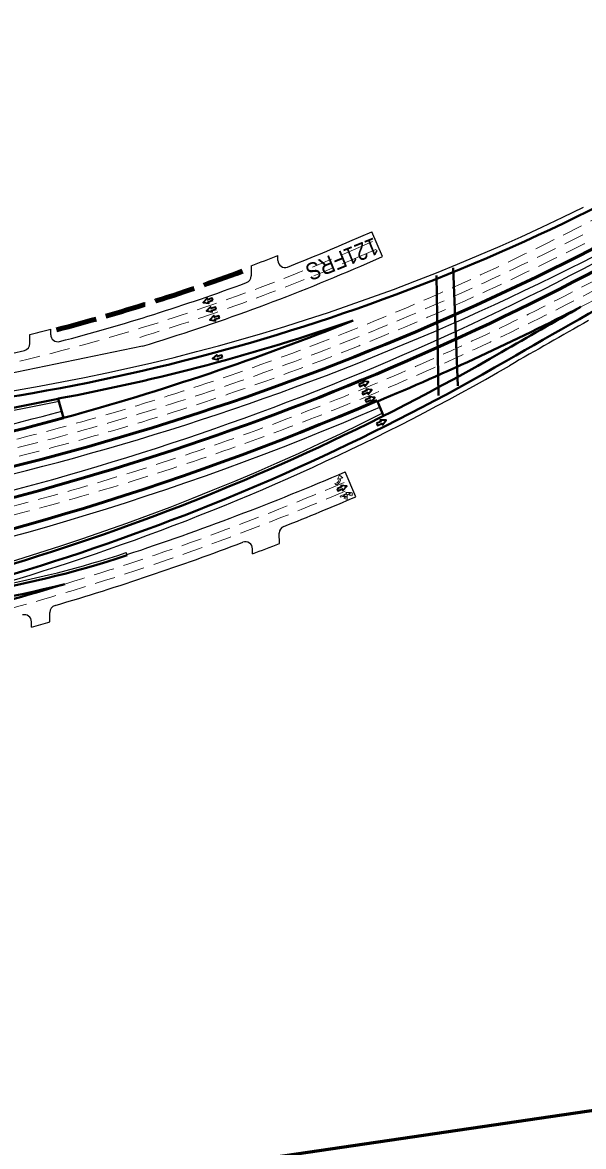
# Model space of a CAD drawing. Extents: x 2329387 to 2347382, y 6951580 to 6987999.
# Drawn here: x 2336392 to 2337180, y 6964242 to 6965820 of the extents above; entities that cross this region are included whole.
import ezdxf

# ---------------------------------------------------------------- set-up
doc = ezdxf.new("R2010")
doc.units = 0
doc.header["$LTSCALE"] = 9.6
doc.header["$PDMODE"] = 32
doc.header["$PDSIZE"] = 4.8
doc.linetypes.add('LONG_DASHED', pattern=[7.5, 6, -1.5])
doc.linetypes.add('MEDIUM_DASHED', pattern=[4.5, 3, -1.5])
for name, color, linetype, lineweight in [('26', 7, 'Continuous', 53), ('27', 7, 'Continuous', 40), ('28', 7, 'Continuous', 25), ('30', 7, 'Continuous', 13), ('41', 7, 'Continuous', 35), ('50', 7, 'MEDIUM_DASHED', 13), ('59', 7, 'LONG_DASHED', 90), ('62', 7, 'Continuous', 60), ('63', 7, 'Continuous', 25)]:
    doc.layers.add(name, color=color, linetype=linetype, lineweight=lineweight)
doc.layers.add('40', color=7, linetype='Continuous')

msp = doc.modelspace()

# ---------------------------------------------------------------- linework, layer by layer
at = {"layer": '26'}
for centre, radius, start, end in [((2335453.211, 6968900.408), 3817.469, 278.35573, 300.65952), ((2335400.739, 6968870.593), 3843.719, 278.81536, 299.60537), ((2335348.901, 6968850.035), 3879.719, 279.60989, 293.40387), ((2335453.211, 6968900.408), 3769.469, 278.35579, 285.32717)]:
    msp.add_arc(centre, radius, start, end, dxfattribs=at)
at = {"layer": '26', "lineweight": 25}
for centre, radius, start, end in [((2335453.211, 6968900.408), 3827.469, 278.35573, 300.65952), ((2335400.739, 6968870.593), 3833.719, 278.81536, 299.60537), ((2335348.901, 6968850.035), 3889.719, 279.60989, 293.40175), ((2335453.211, 6968900.408), 3759.469, 278.35579, 285.32717)]:
    msp.add_arc(centre, radius, start, end, dxfattribs=at)
at = {"layer": '27'}
for p, q in [((2336442.194, 6965292.014), (2336449.596, 6965265.01)), ((2336898.919, 6965267.974), (2336890.472, 6965288.287))]:
    msp.add_line(p, q, dxfattribs=at)
at = {"layer": '27', "lineweight": 25}
msp.add_line((2336538.921, 6965072.242), (2336537.666, 6965076.04), dxfattribs=at)
at = {"layer": '27'}
for centre, radius, start, end in [((2339406.145, 6959556.474), 7976, 170.51466, 170.51466), ((2335914.539, 6968122.19), 2864.789, 275.56071, 300.68463), ((2342801.708, 6955421.615), 11459.156, 118.82398, 120.00238), ((2335400.739, 6968870.593), 3879.719, 292.58041, 297.23352), ((2342801.708, 6955421.615), 11473.156, 119.36174, 120.00238), ((2335914.539, 6968122.19), 2878.789, 280.56067, 289.09494), ((2335453.211, 6968900.408), 3769.469, 285.32717, 291.85272), ((2335434.579, 6968180.635), 3260.044, 278.35573, 300.00238), ((2335434.579, 6968180.635), 3274.044, 278.35573, 300.00238), ((2338670.145, 6954065.803), 11445.156, 101.22505, 102.56422), ((2336093.959, 6966419.035), 1418.394, 278.65967, 288.28285), ((2336093.959, 6966419.035), 1432.394, 274.60744, 284.44642), ((2335351.623, 6968665.906), 3796.719, 283.76869, 286.8364)]:
    msp.add_arc(centre, radius, start, end, dxfattribs=at)
at = {"layer": '27', "lineweight": 25}
for centre, radius, start, end in [((2335914.539, 6968122.19), 2856.789, 275.56071, 296.28739), ((2342801.708, 6955421.615), 11451.156, 119.36378, 120.00238), ((2335434.579, 6968180.635), 3282.044, 278.35573, 300.00238), ((2338670.145, 6954065.803), 11441.156, 101.22361, 102.56422), ((2335434.579, 6968180.635), 3256.044, 278.35573, 296.69097), ((2336093.959, 6966419.035), 1414.394, 280.11263, 288.28285)]:
    msp.add_arc(centre, radius, start, end, dxfattribs=at)
at = {"layer": '28'}
for p, q in [((2336851.795, 6965512.989), (2336882.568, 6965526.287)), ((2336897.641, 6965491.404), (2336882.568, 6965526.287)), ((2336750.537, 6965486.075), (2336750.485, 6965492.951)), ((2336866.861, 6965478.104), (2336897.641, 6965491.404)), ((2336712.979, 6965478.605), (2336713.101, 6965464.352)), ((2336431.554, 6965381.835), (2336431.527, 6965389.584)), ((2336402.274, 6965369.41), (2336402.235, 6965382.133)), ((2336560.342, 6965365.66), (2336302.2, 6965312.166)), ((2336860.023, 6965154.458), (2336845.025, 6965189.373)), ((2336752.637, 6965088.761), (2336752.575, 6965103.38)), ((2336714.981, 6965074.24), (2336714.928, 6965081.203)), ((2336404.711, 6964971.341), (2336404.603, 6964979.007)), ((2336430.494, 6964978.787), (2336430.436, 6964992.096))]:
    msp.add_line(p, q, dxfattribs=at)
for centre, radius, start, end in [((2335715.816, 6968141.837), 2863.789, 291.47419, 293.37016), ((2335715.816, 6968141.837), 2843.789, 290.52683, 291.33588), ((2336760.537, 6965486.15), 10, 180.43476, 291.47419), ((2335715.816, 6968141.837), 2901.789, 286.92001, 293.37001), ((2335715.816, 6968141.837), 2863.789, 284.7325, 290.24016), ((2336703.101, 6965464.267), 10, 290.24015, 0.48871), ((2335715.816, 6968141.837), 2843.789, 283.9677, 284.57665), ((2336441.553, 6965381.87), 10, 180.19786, 284.7325), ((2335715.816, 6968141.837), 2863.789, 278.38524, 283.71181), ((2336392.274, 6965369.38), 10, 283.71182, 0.17378), ((2335351.623, 6968665.906), 3783.719, 288.28285, 293.24673), ((2335351.623, 6968665.906), 3821.719, 291.60646, 293.24673), ((2336762.575, 6965103.423), 10, 111.60646, 180.24506), ((2335351.623, 6968665.906), 3821.719, 286.50851, 290.68224), ((2336704.928, 6965081.127), 10, 0.43315, 110.68224), ((2335351.623, 6968665.906), 3841.719, 290.78622, 291.38814), ((2336440.436, 6964992.14), 10, 106.50851, 180.24816), ((2336394.604, 6964978.866), 10, 0.81008, 105.79501), ((2335351.623, 6968665.906), 3841.719, 285.90951, 286.30975)]:
    msp.add_arc(centre, radius, start, end, dxfattribs=at)
at = {"layer": '30'}
for points in [[(2336836.724, 6965180.042), (2336834.047, 6965178.979), (2336837.085, 6965184.775)], [(2336837.085, 6965184.775), (2336841.867, 6965180.819), (2336838.801, 6965180.38)], [(2336833.255, 6965171.725), (2336831.472, 6965171.014), (2336830.705, 6965172.947), (2336832.282, 6965173.572)], [(2336852.372, 6965160.475), (2336845.954, 6965160.38), (2336847.065, 6965158.884), (2336837.789, 6965155.201), (2336838.365, 6965153.751), (2336839.693, 6965154.278)], [(2336842.066, 6965155.866), (2336847.419, 6965157.992), (2336847.637, 6965156.142), (2336852.372, 6965160.475)], [(2336845.212, 6965153.199), (2336843.205, 6965152.402), (2336847.772, 6965150.6), (2336847.962, 6965155.324), (2336846.298, 6965153.859)]]:
    msp.add_lwpolyline(points, dxfattribs=at)
for centre, radius, start, end in [((2336829.684, 6965180.116), 7.04, 291.64865, 359.39939), ((2336829.684, 6965180.116), 9.12, 293.04957, 1.65818), ((2336841.612, 6965149.446), 5.2, 46.20185, 111.65786), ((2336841.612, 6965149.446), 6.436, 43.28304, 85.96707)]:
    msp.add_arc(centre, radius, start, end, dxfattribs=at)
msp.add_point((2336853.332, 6965158.059), dxfattribs=at)
at = {"layer": '41'}
for points in [[(2336659.216, 6965430.072), (2336658.245, 6965432.911), (2336651.805, 6965430.707), (2336651.016, 6965433.014), (2336645.427, 6965427.107), (2336653.462, 6965425.863), (2336652.776, 6965427.868)], [(2336663.933, 6965417.786), (2336663.036, 6965420.65), (2336656.54, 6965418.614), (2336655.812, 6965420.94), (2336650.071, 6965415.181), (2336658.072, 6965413.728), (2336657.438, 6965415.751)], [(2336668.724, 6965405.525), (2336667.827, 6965408.389), (2336661.331, 6965406.353), (2336660.602, 6965408.679), (2336654.862, 6965402.92), (2336662.863, 6965401.467), (2336662.229, 6965403.49)], [(2336672.655, 6965350.005), (2336671.97, 6965352.926), (2336665.343, 6965351.372), (2336664.786, 6965353.745), (2336658.639, 6965348.423), (2336666.512, 6965346.387), (2336666.028, 6965348.451)], [(2336864.404, 6965312.055), (2336865.527, 6965309.272), (2336871.839, 6965311.819), (2336872.751, 6965309.558), (2336878.014, 6965315.756), (2336869.923, 6965316.567), (2336870.716, 6965314.601)], [(2336868.923, 6965300.878), (2336870.045, 6965298.096), (2336876.358, 6965300.642), (2336877.269, 6965298.382), (2336882.533, 6965304.58), (2336874.442, 6965305.391), (2336875.235, 6965303.425)], [(2336873.28, 6965290.193), (2336874.403, 6965287.41), (2336880.715, 6965289.957), (2336881.627, 6965287.696), (2336886.891, 6965293.895), (2336878.8, 6965294.705), (2336879.593, 6965292.74)], [(2336889.155, 6965257.148), (2336890.453, 6965254.442), (2336896.59, 6965257.386), (2336897.645, 6965255.189), (2336902.502, 6965261.71), (2336894.376, 6965262.003), (2336895.292, 6965260.092)], [(2336833.635, 6965165.6), (2336834.742, 6965162.811), (2336841.068, 6965165.323), (2336841.968, 6965163.057), (2336847.265, 6965169.227), (2336839.179, 6965170.082), (2336839.961, 6965168.112)]]:
    msp.add_lwpolyline(points, close=True, dxfattribs=at)
at = {"layer": '50'}
for p, q in [((2336856.945, 6965501.053), (2336887.724, 6965514.353)), ((2336861.705, 6965490.037), (2336892.484, 6965503.338))]:
    msp.add_line(p, q, dxfattribs=at)
for centre, radius, start, end in [((2335453.211, 6968900.408), 3781.469, 278.35579, 300.65952), ((2335453.211, 6968900.408), 3793.469, 278.35573, 300.65952), ((2335453.211, 6968900.408), 3805.469, 278.35573, 300.65952), ((2335400.739, 6968870.593), 3855.719, 278.81536, 299.60537), ((2335400.739, 6968870.593), 3867.719, 278.81536, 299.60537), ((2335715.816, 6968141.837), 2876.789, 278.35573, 293.37001), ((2335400.739, 6968870.593), 3879.719, 297.23352, 299.60537), ((2335715.816, 6968141.837), 2888.789, 286.92001, 293.37001), ((2335351.623, 6968665.906), 3808.719, 278.35596, 293.24673), ((2335351.623, 6968665.906), 3796.719, 286.8364, 293.24673)]:
    msp.add_arc(centre, radius, start, end, dxfattribs=at)
at = {"layer": '59'}
msp.add_arc((2335715.816, 6968141.837), 2846.789, 284.7325, 290.24016, dxfattribs=at)
at = {"layer": '62'}
msp.add_lwpolyline([(2338114.665, 6964428.225), (2329704.893, 6963193.017), (2329428.787, 6965072.851), (2337838.559, 6966308.058)], close=True, dxfattribs=at)
at = {"layer": '63', "lineweight": 40}
for p, q in [((2336996.462, 6965475.699), (2337002.996, 6965309.851)), ((2336973.472, 6965465.108), (2336976.141, 6965296.694))]:
    msp.add_line(p, q, dxfattribs=at)

# ---------------------------------------------------------------- texts
at = {"layer": '40', "width": 0.9}
msp.add_text('121FRS', height=24, rotation=201.965, dxfattribs=at).set_placement((2336885.554, 6965518.845))

doc.saveas('drawing.dxf')
